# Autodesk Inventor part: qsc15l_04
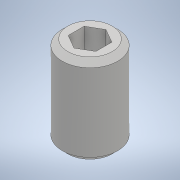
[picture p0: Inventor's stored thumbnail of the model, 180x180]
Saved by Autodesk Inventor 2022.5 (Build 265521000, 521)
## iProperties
Part Number: qsc15l_04
Material: 一般
Document SubType Name: Modeling
Designer: ImaoCorp
Density: 1 g/cm^3
Appearance: 既定
Author: ImaoCorp
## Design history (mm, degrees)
feature "qsc15l_04"
node "ソリッド1"
